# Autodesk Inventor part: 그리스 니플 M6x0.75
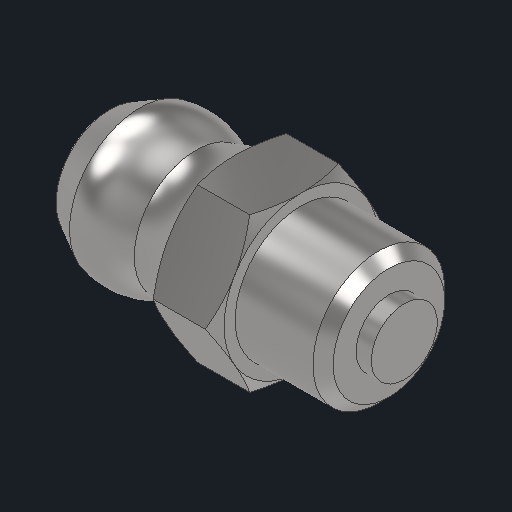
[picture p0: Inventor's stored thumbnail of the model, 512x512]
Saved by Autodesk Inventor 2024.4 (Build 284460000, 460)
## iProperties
Created: 2025-10
Part Number: 그리스 니플 M6x0.75
Material: 강철, 연강
Description: 윤활 니플, 원추 유형 A
Document SubType Name: Modeling
Designer: user
Density: 7.85 g/cm^3
Appearance: 기본값
Author: jhkim
Sending System: Autodesk Inventor 2026
Preprocessor: ST-DEVELOPER v20.1
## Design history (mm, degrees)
feature "Solid1"
node "솔리드1"
